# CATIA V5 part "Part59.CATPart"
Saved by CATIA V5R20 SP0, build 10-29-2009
Part number: FA 042200-1
Revision: ANY
Definition: UNKNOWN
Nomenclature: FA 042200-1
Source: Unknown
Bounding box of the stored display mesh (mm): x 0.374 to 3.8, y -1.58 to 1.58, z -1.58 to 1.58
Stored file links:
  C:\Users\Utente\Desktop\IO LAVORO\3D X SITO CF\CUMSA\3D files FA\FA 042212-20\Part59.CATPart

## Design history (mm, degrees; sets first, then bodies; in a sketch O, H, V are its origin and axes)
Body1 "Cortar-Extruir2" (main body)
  Solid1: solid without history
